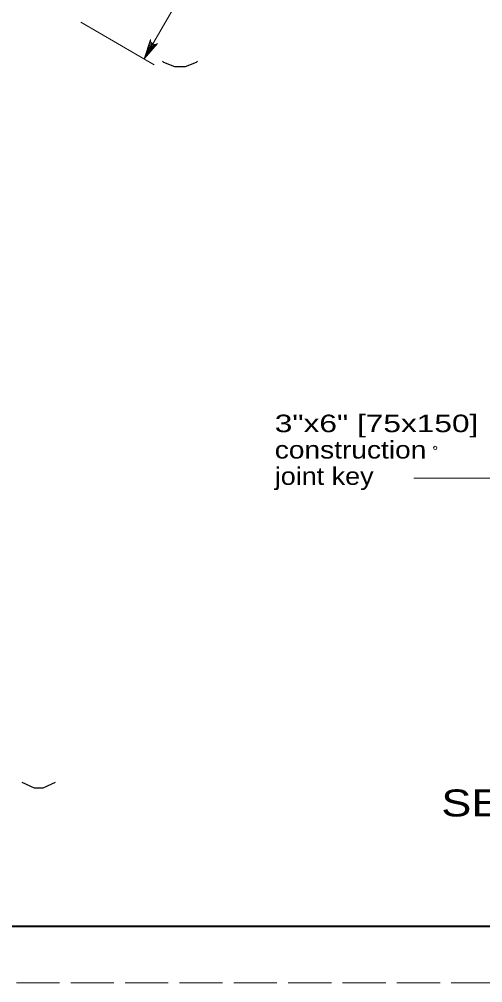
# Model space of a CAD drawing. Extents: x 1083.1 to 1117.1, y 697.4 to 743.4.
# Drawn here: x 1098.64 to 1102.77, y 721.35 to 729.93 of the extents above; entities that cross this region are included whole.
import ezdxf

# ---------------------------------------------------------------- set-up
doc = ezdxf.new("R2010")
doc.units = 0
doc.header["$LTSCALE"] = 0.064
doc.linetypes.add('LONG_DASHED', pattern=[7.5, 6, -1.5])
doc.layers.add('1', color=7, linetype='Continuous', lineweight=13)

msp = doc.modelspace()

# ---------------------------------------------------------------- linework, layer by layer
at = {"layer": '1'}
for p, q in [((1099.188, 729.90542), (1099.8405, 729.52683)), ((1099.81158, 729.72908), (1099.75058, 729.57925)), ((1099.81842, 729.71883), (1099.75058, 729.57925)), ((1099.82742, 729.71175), (1099.75058, 729.57925)), ((1099.85333, 729.70708), (1099.75058, 729.57925)), ((1099.84125, 729.70692), (1099.75058, 729.57925))]:
    msp.add_line(p, q, dxfattribs=at)
at = {"layer": '1', "linetype": 'LONG_DASHED'}
msp.add_lwpolyline([(1083.12642, 721.35408), (1117.12642, 721.35408), (1117.12642, 743.35408), (1083.12642, 743.35408)], close=True, dxfattribs=at)
at = {"layer": '1', "lineweight": 25}
msp.add_lwpolyline([(1085.12642, 742.85408), (1116.62642, 742.85408), (1116.62642, 721.85408), (1085.12642, 721.85408)], close=True, dxfattribs=at)
at = {"layer": '1', "lineweight": 40}
msp.add_lwpolyline([(1085.12642, 742.85408), (1116.62642, 742.85408), (1116.62642, 721.85408), (1085.12642, 721.85408)], close=True, dxfattribs=at)
msp.add_lwpolyline([(1085.12642, 742.85408), (1116.62642, 742.85408), (1116.62642, 721.85408), (1085.12642, 721.85408)], close=True, dxfattribs=at)
at = {"layer": '1'}
for points in [[(1099.75058, 729.57925), (1100.15, 730.26808), (1101.70858, 732.95575)], [(1099.87, 729.71458), (1099.75058, 729.57925), (1099.80875, 729.75008)], [(1103.37033, 725.37217), (1102.92683, 725.84642), (1102.15325, 725.84642)]]:
    msp.add_lwpolyline(points, dxfattribs=at)
at = {"layer": '1', "lineweight": 25}
for points in [[(1100.22592, 729.55942), (1100.214, 729.54733), (1100.11592, 729.50767), (1100.02442, 729.50767), (1099.92625, 729.54733), (1099.91433, 729.55942)], [(1098.66208, 723.13992), (1098.77225, 723.08992), (1098.85275, 723.08992), (1098.96292, 723.13992)]]:
    msp.add_lwpolyline(points, dxfattribs=at)
at = {"layer": '1'}
msp.add_circle((1102.34379, 726.11513), 0.01523, dxfattribs=at)
msp.add_arc((1099.84649, 729.74473), 0.0382, 171.98386, 307.80999, dxfattribs=at)

# ---------------------------------------------------------------- texts
for s, height, width, p in [('3"x6" [75x150]', 0.156, 1.35, (1100.9145, 726.25567)), ('construction', 0.156, 1.2, (1100.9145, 726.021)), ('joint key', 0.156, 1.15, (1100.9145, 725.78633)), ('SECTION C-C', 0.24, 1.25, (1102.3975, 722.83442))]:
    msp.add_text(s, height=height, dxfattribs=dict(at, width=width)).set_placement(p)

doc.saveas('drawing.dxf')
